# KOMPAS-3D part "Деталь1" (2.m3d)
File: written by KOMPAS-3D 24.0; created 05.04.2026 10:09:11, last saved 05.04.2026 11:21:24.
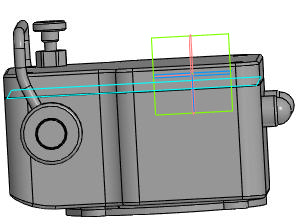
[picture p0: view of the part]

Document properties: Автор: R2D2; Полное имя файла: E:\Работа\Зайцев\Аксессуары для пневмоприводов\Ручной дублер DN.ru\MON3-700-T38-ISO Ручной дублер DN.ru\исходные материалы\2.m3d

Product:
- Body: Тело 2  | qty 1
    Масса: 16.14074
- Part/product: Деталь1
    Масса: 21.052029
    additional columns: Типовые

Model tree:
1. Операция без истории:1
2. Эскиз:1
3. Элемент выдавливания:3
     Расстояние 1 = 500
4. Смещенная плоскость:1  (with: Грань.Операция без истории:1)
     Расстояние = 15
5. Эскиз:2  (with: Ребро.Операция без истории:1)
6. Элемент выдавливания:4
     Расстояние 2 = 0.5
7. Элемент выдавливания:5  (with: Грань.Операция без истории:1)
     Расстояние 1 = 0.5
8. Эскиз:3  (with: Грань.Операция без истории:1)
9. Элемент выдавливания:6
     Расстояние 1 = 30.2931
